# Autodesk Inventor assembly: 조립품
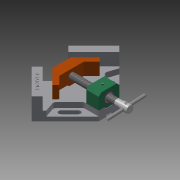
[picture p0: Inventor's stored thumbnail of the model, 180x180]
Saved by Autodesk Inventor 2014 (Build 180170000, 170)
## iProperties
Created: 2019-04
Part Number: 조립품
Document SubType Name: Assembly
Designer: kh
Author: kh
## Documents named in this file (11)
- C:\Users\kh\Desktop\490407V1024\답안조립품.iam
- C:\Users\kh\Desktop\490407V1024\본체.ipt
- C:\Users\kh\Desktop\490407V1024\리드스크류.ipt
- C:\Users\kh\Desktop\490407V1024\멈춤나사 M4x5.ipt
- C:\Users\kh\Desktop\490407V1024\멈춤나사 M4x10.ipt
- C:\Users\kh\Desktop\490407V1024\볼트 M4x16.ipt
- C:\Users\kh\Desktop\490407V1024\부시.ipt
- C:\Users\kh\Desktop\490407V1024\서포트.ipt
- C:\Users\kh\Desktop\490407V1024\조.ipt
- C:\Users\kh\Desktop\490407V1024\평행 핀 2.5x24.ipt
- C:\Users\kh\Desktop\490407V1024\핸들.ipt
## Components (1 placed, 1 different names)
1. 핸들:1 — Mate:4, Mate:5, Mate:6, Angle:7
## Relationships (4: Mate 3, Angle 1)
- Mate:4: 핸들:1
- Mate:5: 핸들:1
- Mate:6: 핸들:1
- Angle:7: 핸들:1
